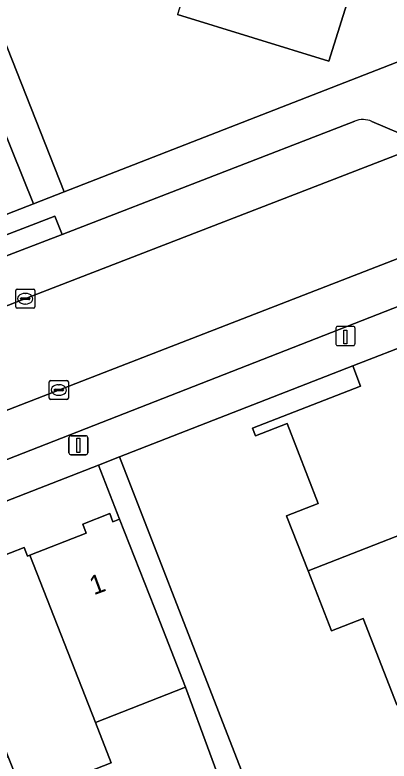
# Model space of a CAD drawing. Extents: x 159680 to 160786, y 387323 to 388340.
# Drawn here: x 159948.85 to 159968.51, y 387787.43 to 387826.64 of the extents above; entities that cross this region are included whole.
import ezdxf

# ---------------------------------------------------------------- set-up
doc = ezdxf.new("R2010")
doc.units = 0
for name, color, linetype in [('IMGEO_Erf', 7, 'Continuous'), ('IMGEO_Kolk', 7, 'Continuous'), ('IMGEO_Laadpaal', 7, 'Continuous'), ('IMGEO_Lichtmast', 7, 'Continuous'), ('IMGEO_Pand', 7, 'Continuous'), ('IMGEO_Pand_nummerreeks', 7, 'Continuous'), ('IMGEO_Parkeervlak_open', 7, 'Continuous'), ('IMGEO_Rijbaan_lokaal_open', 7, 'Continuous'), ('IMGEO_Voetpad_open', 7, 'Continuous')]:
    doc.layers.add(name, color=color, linetype=linetype)

msp = doc.modelspace()

# ---------------------------------------------------------------- linework, layer by layer
at = {"layer": 'IMGEO_Erf'}
for points in [[(159966.687, 387844.688), (159952.097, 387882.134), (159929.514, 387872.862), (159951.443, 387817.344), (159972.219, 387825.439)], [(159968.082, 387832.924), (159965.349, 387824.2), (159957.39, 387826.656)], [(159923.671, 387806.523), (159949.825, 387816.714), (159944.202, 387830.659)], [(159968.914, 387790.384), (159967.149, 387794.916), (159965.484, 387794.267), (159964.252, 387797.428), (159963.148, 387800.263), (159963.128, 387800.315), (159964.793, 387800.963), (159963.158, 387805.161), (159961.492, 387804.512), (159961.333, 387804.921), (159967.011, 387807.133), (159966.6, 387808.188), (159954.35, 387803.411), (159975.149, 387749.886)], [(159930.956, 387791.493), (159935.682, 387793.345), (159940.268, 387795.143), (159944.684, 387796.874), (159944.864, 387796.414), (159945.036, 387796.481), (159948.051, 387797.663), (159947.883, 387798.09), (159949.328, 387798.656), (159949.51, 387798.191), (159949.638, 387798.241), (159952.595, 387799.4), (159952.41, 387799.873), (159953.833, 387800.43), (159954.003, 387799.998), (159954.351, 387800.134), (159953.242, 387802.979), (159928.783, 387793.44)], [(159927.698, 387790.952), (159933.909, 387775.155), (159941.506, 387778.149), (159944.117, 387779.178), (159945.403, 387775.915), (159948.606, 387777.091), (159956.979, 387780.068), (159956.952, 387780.135), (159955.964, 387782.626), (159960.373, 387784.377), (159957.811, 387791.306), (159953.084, 387789.453), (159953.913, 387787.338), (159949.326, 387785.54), (159948.497, 387787.655), (159943.909, 387785.857), (159939.252, 387784.031), (159934.596, 387782.206), (159930.956, 387791.493)]]:
    msp.add_lwpolyline(points, dxfattribs=at)
at = {"layer": 'IMGEO_Kolk'}
for p, q in [((159948.966, 387812.224), (159949.818, 387812.224)), ((159948.891, 387811.298), (159948.891, 387812.15)), ((159949.379, 387812.004), (159949.404, 387812.004)), ((159949.892, 387812.15), (159949.892, 387811.298)), ((159949.15, 387811.718), (159949.15, 387811.73)), ((159949.588, 387811.681), (159949.19, 387811.681)), ((159949.193, 387811.767), (159949.591, 387811.767)), ((159949.402, 387811.444), (159949.377, 387811.444)), ((159949.634, 387811.73), (159949.634, 387811.718)), ((159949.818, 387811.224), (159948.966, 387811.224)), ((159950.656, 387806.5), (159950.656, 387807.352)), ((159950.731, 387807.426), (159951.583, 387807.426)), ((159951.144, 387807.206), (159951.169, 387807.206)), ((159951.657, 387807.352), (159951.657, 387806.5)), ((159950.915, 387806.92), (159950.915, 387806.932)), ((159951.353, 387806.883), (159950.955, 387806.883)), ((159950.958, 387806.969), (159951.356, 387806.969)), ((159951.399, 387806.932), (159951.399, 387806.92)), ((159951.583, 387806.426), (159950.731, 387806.426)), ((159951.167, 387806.646), (159951.142, 387806.646))]:
    msp.add_line(p, q, dxfattribs=at)
for points in [[(159948.966, 387812.224), (159949.818, 387812.224)], [(159948.891, 387811.298), (159948.891, 387812.15)], [(159949.892, 387812.15), (159949.892, 387811.298)], [(159949.818, 387811.224), (159948.966, 387811.224)], [(159950.656, 387806.5), (159950.656, 387807.352)], [(159950.731, 387807.426), (159951.583, 387807.426)], [(159951.657, 387807.352), (159951.657, 387806.5)], [(159951.583, 387806.426), (159950.731, 387806.426)]]:
    msp.add_lwpolyline(points, dxfattribs=at)
for centre, radius, start, end in [((159948.968, 387812.148), 0.0765, 91.552, 178.448), ((159948.968, 387812.148), 0.0765, 91.552, 178.448), ((159949.816, 387812.148), 0.0765, 1.552, 88.448), ((159949.816, 387812.148), 0.0765, 1.552, 88.448), ((159949.19, 387811.727), 0.0403, 85.8775, 175.7526), ((159949.187, 387811.717), 0.0366, 178.938, 274.7102), ((159949.591, 387811.724), 0.043, 264.8664, 352.4533), ((159949.595, 387811.729), 0.0386, 1.7309, 96.639), ((159948.968, 387811.3), 0.0765, 181.552, 268.448), ((159948.968, 387811.3), 0.0765, 181.552, 268.448), ((159949.816, 387811.3), 0.0765, 271.552, 358.448), ((159949.816, 387811.3), 0.0765, 271.552, 358.448), ((159950.733, 387807.35), 0.0765, 91.552, 178.448), ((159950.733, 387807.35), 0.0765, 91.552, 178.448), ((159951.581, 387807.35), 0.0765, 1.552, 88.448), ((159951.581, 387807.35), 0.0765, 1.552, 88.448), ((159950.955, 387806.929), 0.0403, 85.8775, 175.7526), ((159950.952, 387806.919), 0.0366, 178.938, 274.7102), ((159951.356, 387806.926), 0.043, 264.8664, 352.4533), ((159951.36, 387806.931), 0.0386, 1.7309, 96.639), ((159950.733, 387806.502), 0.0765, 181.552, 268.448), ((159950.733, 387806.502), 0.0765, 181.552, 268.448), ((159951.581, 387806.502), 0.0765, 271.552, 358.448), ((159951.581, 387806.502), 0.0765, 271.552, 358.448)]:
    msp.add_arc(centre, radius, start, end, dxfattribs=at)
for centre, major_axis, ratio, start_param, end_param in [((159949.378, 387811.724), (-0.387, 0.002), 0.722429, 4.712389, 7.853982), ((159949.403, 387811.724), (-0.39, 0.002), 0.717154, 1.570796, 4.712389), ((159951.143, 387806.926), (-0.387, 0.002), 0.722429, 4.712389, 7.853982), ((159951.168, 387806.926), (-0.39, 0.002), 0.717154, 1.570796, 4.712389)]:
    msp.add_ellipse(centre, major_axis=major_axis, ratio=ratio, start_param=start_param, end_param=end_param, dxfattribs=at)
at = {"layer": 'IMGEO_Laadpaal'}
for p, q in [((159966.638, 387810.265), (159965.797, 387810.265)), ((159966.638, 387810.265), (159965.797, 387810.265)), ((159965.722, 387810.181), (159965.722, 387809.34)), ((159965.722, 387810.181), (159965.722, 387809.34)), ((159966.722, 387809.349), (159966.722, 387810.19)), ((159966.722, 387809.349), (159966.722, 387810.19)), ((159965.806, 387809.265), (159966.647, 387809.265)), ((159965.806, 387809.265), (159966.647, 387809.265))]:
    msp.add_line(p, q, dxfattribs=at)
msp.add_lwpolyline([(159966.137, 387810.078), (159966.297, 387810.078), (159966.297, 387809.345), (159966.137, 387809.345), (159966.137, 387810.078)], dxfattribs=at)
for centre, start, end in [((159965.8, 387810.187), 92.4484, 184.2845), ((159965.8, 387810.187), 92.4484, 184.2845), ((159966.644, 387810.187), 2.4484, 94.2845), ((159966.644, 387810.187), 2.4484, 94.2845), ((159965.8, 387809.343), 182.4484, 274.2845), ((159965.8, 387809.343), 182.4484, 274.2845), ((159966.644, 387809.343), 272.4484, 4.2845), ((159966.644, 387809.343), 272.4484, 4.2845)]:
    msp.add_arc(centre, 0.0779, start, end, dxfattribs=at)
at = {"layer": 'IMGEO_Lichtmast'}
for p, q in [((159951.683, 387803.621), (159951.683, 387804.421)), ((159951.683, 387804.421), (159951.683, 387803.621)), ((159951.783, 387804.521), (159952.573, 387804.521)), ((159952.573, 387804.521), (159951.783, 387804.521)), ((159952.673, 387804.421), (159952.673, 387803.621)), ((159952.673, 387803.621), (159952.673, 387804.421)), ((159952.573, 387803.521), (159951.783, 387803.521)), ((159951.783, 387803.521), (159952.573, 387803.521))]:
    msp.add_line(p, q, dxfattribs=at)
msp.add_lwpolyline([(159952.103, 387804.396), (159952.253, 387804.396), (159952.253, 387803.646), (159952.103, 387803.646), (159952.103, 387804.396)], dxfattribs=at)
for centre, start, end in [((159951.783, 387804.421), 90, 180), ((159951.783, 387804.421), 90, 180), ((159952.573, 387804.421), 0, 90), ((159952.573, 387804.421), 360, 90), ((159951.783, 387803.621), 180, 270), ((159951.783, 387803.621), 180, 270), ((159952.573, 387803.621), 270, 0), ((159952.573, 387803.621), 270, 0)]:
    msp.add_arc(centre, 0.1, start, end, dxfattribs=at)
at = {"layer": 'IMGEO_Pand'}
for points in [[(159968.082, 387832.924), (159965.35, 387833.78), (159966.352, 387836.977), (159964.209, 387837.649), (159962.304, 387831.573), (159959.232, 387832.534), (159958.885, 387831.428), (159957.39, 387826.656), (159965.349, 387824.2)], [(159973.294, 387810.795), (159966.6, 387808.188), (159967.011, 387807.133), (159961.333, 387804.921), (159961.492, 387804.512), (159963.158, 387805.161), (159964.793, 387800.963), (159963.128, 387800.315), (159963.148, 387800.263), (159964.252, 387797.428), (159972.692, 387800.718), (159971.75, 387803.134), (159975.357, 387805.499)], [(159953.084, 387789.453), (159957.811, 387791.306), (159956.176, 387795.479), (159954.351, 387800.134), (159954.003, 387799.998), (159953.833, 387800.43), (159952.41, 387799.873), (159952.595, 387799.4), (159949.638, 387798.241)], [(159972.692, 387800.718), (159964.252, 387797.428), (159965.484, 387794.267), (159967.149, 387794.916), (159968.914, 387790.384), (159979.653, 387794.57), (159978.132, 387798.474), (159973.634, 387798.3)], [(159949.638, 387798.241), (159949.51, 387798.191), (159949.328, 387798.656), (159947.883, 387798.09), (159948.051, 387797.663), (159945.036, 387796.481), (159948.497, 387787.655), (159949.326, 387785.54), (159953.913, 387787.338), (159953.084, 387789.453)]]:
    msp.add_lwpolyline(points, close=True, dxfattribs=at)
at = {"layer": 'IMGEO_Parkeervlak_open'}
for points in [[(159966.707, 387821.058), (159951.326, 387815.106), (159947.936, 387813.795), (159930.079, 387806.885)], [(159969.838, 387820.091), (159967.611, 387821.043)], [(159926.446, 387802.791), (159949.224, 387811.657), (159970.967, 387820.07)], [(159972.771, 387815.3), (159946.794, 387805.237), (159929.996, 387798.667)], [(159934.755, 387797.935), (159969.917, 387811.687)]]:
    msp.add_lwpolyline(points, dxfattribs=at)
msp.add_arc((159967.141, 387819.94), 1.199, 66.8949, 111.2038, dxfattribs=at)
at = {"layer": 'IMGEO_Rijbaan_lokaal_open'}
msp.add_lwpolyline([(159972.771, 387815.3), (159974.926, 387816.135), (159976.607, 387816.786), (159974.995, 387821.629), (159970.967, 387820.07), (159949.224, 387811.657), (159926.446, 387802.791), (159923.532, 387801.657), (159925.493, 387796.906), (159929.996, 387798.667), (159946.794, 387805.237)], close=True, dxfattribs=at)
at = {"layer": 'IMGEO_Voetpad_open'}
for points in [[(159944.202, 387830.659), (159949.825, 387816.714), (159951.443, 387817.344), (159929.514, 387872.862)], [(159972.219, 387825.439), (159951.443, 387817.344), (159949.825, 387816.714), (159923.671, 387806.523)], [(159930.079, 387806.885), (159947.936, 387813.795), (159947.564, 387814.756), (159950.954, 387816.067), (159951.326, 387815.106), (159966.707, 387821.058)], [(159967.611, 387821.043), (159969.838, 387820.091)], [(159969.917, 387811.687), (159934.755, 387797.935)], [(159953.242, 387802.979), (159954.35, 387803.411), (159966.6, 387808.188), (159973.294, 387810.795), (159974.275, 387811.17)], [(159975.149, 387749.886), (159954.35, 387803.411), (159953.242, 387802.979), (159954.351, 387800.134), (159956.176, 387795.479), (159957.811, 387791.306), (159960.373, 387784.377), (159961.389, 387781.819), (159956.979, 387780.068), (159948.606, 387777.091), (159945.403, 387775.915), (159942.762, 387774.874), (159935.192, 387771.89), (159935.732, 387770.506), (159939, 387771.782), (159943.66, 387773.597), (159949.45, 387775.851), (159961.805, 387780.652), (159962.475, 387778.928), (159963.628, 387775.891), (159964.945, 387772.424), (159966.031, 387769.692), (159967.177, 387766.778), (159968.967, 387762.225)], [(159928.783, 387793.44), (159953.242, 387802.979)]]:
    msp.add_lwpolyline(points, dxfattribs=at)
msp.add_lwpolyline([(159951.326, 387815.106), (159950.954, 387816.067), (159947.564, 387814.756), (159947.936, 387813.795)], close=True, dxfattribs=at)
msp.add_arc((159967.141, 387819.94), 1.199, 66.8949, 111.2038, dxfattribs=at)

# ---------------------------------------------------------------- texts
at = {"layer": 'IMGEO_Pand_nummerreeks'}
msp.add_text('1', height=1, rotation=20.2718, dxfattribs=at).set_placement((159952.996, 387796.137))

doc.saveas('drawing.dxf')
